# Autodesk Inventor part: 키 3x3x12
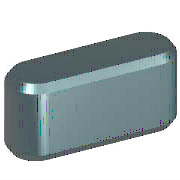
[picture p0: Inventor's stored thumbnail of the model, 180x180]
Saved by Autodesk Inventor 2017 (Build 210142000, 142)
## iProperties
Created: 2012-02
Part Number: 키 3x3x12
Material: 강철, 연강
Description: 키 및 해당 키홈
Document SubType Name: Modeling
Standard: KS B 1311
Designer: mduedu
Standards Organization: KS
Language: ko-KR
Size Designation: 3 x 3 x 12
Categories: <MemberInstance><Categories><Category DisplayName="샤프트 부품" InternalName="7f7aeb1f-a693-4053-b835-cee3144e0d98" Mnemonic="SHFT"><Category DisplayName="키" Interna
Density: 1 g/cm^3
Appearance: 노란색
IsCustomPart: 1
Author: mduedu
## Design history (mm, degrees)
workplane "Work Plane1"
workplane "Work Plane2"
sketch "스케치1"
  geometry: L1 (1.5, 1.5)-(10.5, 1.5); L2 (10.5, -1.5)-(1.5, -1.5); L3 (0, 9.4)-(0, -7.4) reference; L4 (-5, 0)-(30, 0) reference; L5 (12, 0)-(12, 7); A1 r 1.5 centre (1.5, 0) between (1.5, 1.5) and (1.5, -1.5); A2 r 1.5 centre (10.5, 0) between (10.5, -1.5) and (10.5, 1.5)
  constraints: 6 end point, 5 point on circle, 4 tangent, 3 point on line, 2 centre point, 1 horizontal, 1 parallel, 1 perpendicular
  dimensions: "d0" = 1.5 radius of A1 (= 0.5 x PB); "d13" = 1.5 radius of A2 (= 0.5 x PB); "d14" = 12 distance between parallel lines of L5 L3 (= NLG)
extrude "본체1" new body sketch "스케치1" taper "d3" = 0 deg; stored distance "d4" = 10
workplane "Work Plane3"
body "Solid1"
chamfer "모따기1" distance "d8" = 0.25 (= PHH); stored, may be unused: second distance "d9" = 0.25 (= PHH), angle "d15" = 45 deg
other parameters: "d1" = -1.8 (= -PNT), "d2" = 1.2 (= PH - PNT), "NLG" = 12 [user parameter; used in 3 equation terms], "PB" = 3 [user parameter; used in 2 equation terms], "PNT" = 1.8 [user parameter; used in 2 equation terms], "PH" = 3 [user parameter; used in 1 equation term], "PHH" = 0.25 [user parameter; used in 2 equation terms], "d10" = 0, "d16" = 0, "d17" = 0, "d18" = 0, "WDMIN" = 8 [user parameter], "PLB2" = 12 (= NLG) [user parameter], "PLB1" = 12 (= NLG) [user parameter], "RR" = 0.08 [user parameter], "PUEB" = 1.4 [user parameter]
